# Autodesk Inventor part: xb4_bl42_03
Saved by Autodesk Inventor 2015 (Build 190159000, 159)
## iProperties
Created: 2018-05
Part Number: xb4_bl42_03
Checked By: TraceParts S.A.
Material: Generic
Catalog Web Link: www.traceparts.com
Document SubType Name: Modeling
Designer: TraceParts
Density: 1 g/cm^3
Appearance: Default
Company: TraceParts S.A.
Author: TraceParts
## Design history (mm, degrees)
feature "xb4_bl42_03.ipt"
body "Solid1"
